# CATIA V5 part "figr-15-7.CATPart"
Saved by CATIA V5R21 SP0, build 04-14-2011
Part number: Part1
Bounding box of the stored display mesh (mm): x -50 to 50, y -32.5 to 33.5, z -52 to 1
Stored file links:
  D:\CATIA V5R21 E-RESOURCES\CATIA-V5R21\catia-v5r21-prt\c15-catia-v5r20-prt\c15-catia-v5r21-figr-15-7.CATPart
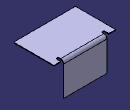
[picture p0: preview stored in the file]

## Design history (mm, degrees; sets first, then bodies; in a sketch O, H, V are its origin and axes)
SheetMetalParameters1: Thickness 1, BendRadius 4, KFactor 0.475772 {= log(min(100,max(20*SheetMetalParameters1.BendRadius,SheetMetalParameters1.Thickness)/SheetMetalParameters1.Thickness))/log(100)/2}, ReliefRadialLength 4, ReliefAxialLength 4, MinimumBendRadius 0
Body1 (main body)
  Sketch1 on xy-plane, origin (0, 0, 0), H (1, 0, 0), V (0, 1, 0)
    line L1 (-50, 32.5) -> (50, 32.5)
    line L2 (50, 32.5) -> (50, -32.5)
    line L3 (50, -32.5) -> (-50, -32.5)
    line L4 (-50, -32.5) -> (-50, 32.5)
    length L1 = 100
    length L2 = 65
    horizontal: L1 H, L3 H
    vertical: L2 V, L4 V
    symmetry: L4 L2 V, L1 L3 H
  Wall1: Thickness 1, Profile Sketch1
  d_NewWallOnEdge1: NewWallOnEdge_Edge edge [face of Wall1 | face of Wall1], NewWallOnEdge_Length 53, NewWallOnEdge_HeightLimitOffset 0, NewWallOnEdge_WidthOffset1 -15, NewWallOnEdge_WidthOffset2 -15, NewWallOnEdge_Angle 90, NewWallOnEdge_BendRadiusValue 4 {= SheetMetalParameters1.BendRadius}, NewWallOnEdge_BendTable SheetMetalParameters1, KFacteur 0.475772 {= log(min(100,max(20*d_NewWallOnEdge1.Radius,SheetMetalParameters1.Thickness)/SheetMetalParameters1.Thickness))/log(100)/2}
